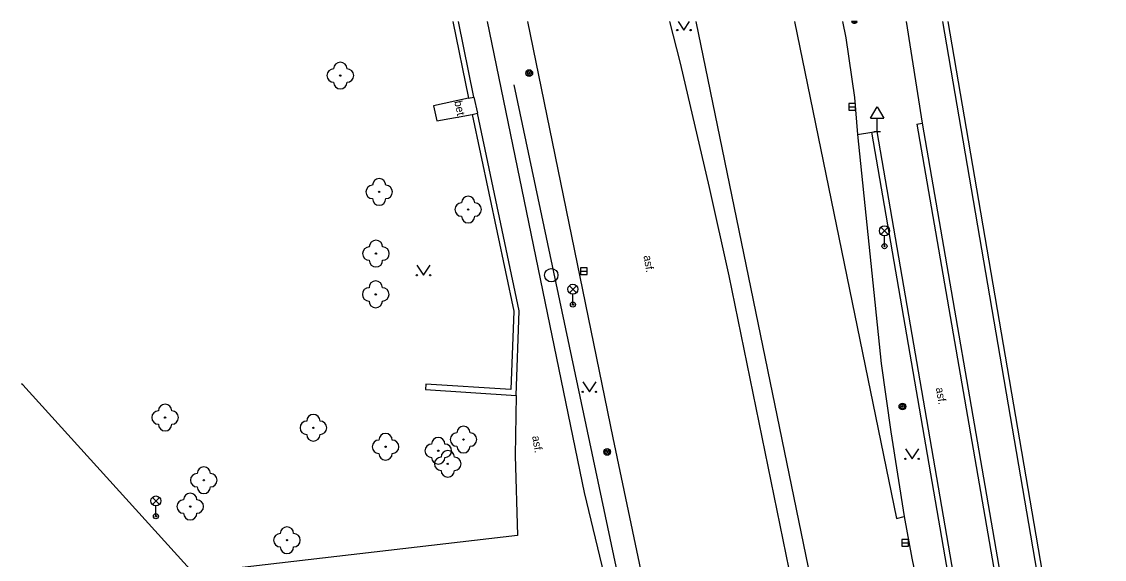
# Model space of a CAD drawing. Extents: x -640201 to -639641, y -1044739 to -1044317.
# Drawn here: x -640198.6 to -640117.4, y -1044357.3 to -1044317 of the extents above; entities that cross this region are included whole.
import ezdxf

# ---------------------------------------------------------------- set-up
doc = ezdxf.new("R2010")
doc.units = 0
for name, color, linetype in [('Ploty', 7, 'Continuous'), ('Popis povrchů', 7, 'Continuous'), ('Rozhraní ploch 1', 7, 'Continuous'), ('Rozhraní ploch 2', 7, 'Continuous'), ('Sloupy_označník', 7, 'Continuous'), ('Zeleň - stromy', 7, 'Continuous'), ('Znaky doprava', 7, 'Continuous'), ('Znaky kanalizace', 7, 'Continuous'), ('Značky doprava', 7, 'Continuous'), ('Značky KM', 7, 'Continuous')]:
    doc.layers.add(name, color=color, linetype=linetype)

msp = doc.modelspace()

# ---------------------------------------------------------------- linework, layer by layer
at = {"layer": 'Ploty'}
for p, q in [((-640117.81, -1044385.35), (-640129.52, -1044317.039)), ((-640117.416, -1044385.282), (-640129.115, -1044317.039)), ((-640161.67, -1044321.76), (-640153.53, -1044360.18))]:
    msp.add_line(p, q, dxfattribs=at)
at = {"layer": 'Rozhraní ploch 1'}
for p, q in [((-640166.227, -1044317.039), (-640165.06, -1044322.78)), ((-640164.67, -1044322.69), (-640165.816, -1044317.039)), ((-640163.663, -1044317.039), (-640156.4, -1044352.32)), ((-640160.645, -1044317.039), (-640154.26, -1044348.23)), ((-640149.17, -1044320.16), (-640149.983, -1044317.039)), ((-640148.017, -1044317.039), (-640139.43, -1044358.78)), ((-640137.033, -1044317.039), (-640136.79, -1044318.26)), ((-640136.79, -1044318.26), (-640136.13, -1044322.73)), ((-640147.01, -1044329.47), (-640149.17, -1044320.16)), ((-640165.06, -1044322.78), (-640164.67, -1044322.69)), ((-640164.67, -1044322.69), (-640164.38, -1044323.9)), ((-640136.13, -1044322.73), (-640135.91, -1044325.49)), ((-640164.78, -1044323.99), (-640164.38, -1044323.9)), ((-640164.78, -1044323.99), (-640161.66, -1044338.74)), ((-640161.26, -1044338.71), (-640164.38, -1044323.9)), ((-640135.91, -1044325.49), (-640134.83, -1044325.32)), ((-640135.91, -1044325.49), (-640134.14, -1044342.66)), ((-640145.53, -1044336.09), (-640147.01, -1044329.47)), ((-640133.97, -1044392.45), (-640145.53, -1044336.09)), ((-640161.66, -1044338.74), (-640161.89, -1044344.61)), ((-640161.5, -1044345.05), (-640161.26, -1044338.71)), ((-640134.14, -1044342.66), (-640133.42, -1044347.78)), ((-640198.47, -1044344.26), (-640198.551, -1044344.171)), ((-640185.68, -1044358.36), (-640198.47, -1044344.26)), ((-640168.26, -1044344.19), (-640168.28, -1044344.6)), ((-640168.28, -1044344.6), (-640161.5, -1044345.05)), ((-640161.89, -1044344.61), (-640168.26, -1044344.19)), ((-640161.5, -1044345.05), (-640161.58, -1044349.55)), ((-640133.42, -1044347.78), (-640132.42, -1044354.12)), ((-640154.26, -1044348.23), (-640149.89, -1044368.95)), ((-640161.58, -1044349.55), (-640161.39, -1044355.53)), ((-640156.4, -1044352.32), (-640154.493, -1044360.164)), ((-640132.42, -1044354.12), (-640131.84, -1044357.24)), ((-640161.39, -1044355.53), (-640185.68, -1044358.36)), ((-640131.84, -1044357.24), (-640125.11, -1044389.4))]:
    msp.add_line(p, q, dxfattribs=at)
at = {"layer": 'Rozhraní ploch 2'}
for p, q in [((-640140.636, -1044317.039), (-640133, -1044354.26)), ((-640132.275, -1044317.039), (-640131.08, -1044324.64)), ((-640165.06, -1044322.78), (-640167.68, -1044323.35)), ((-640167.68, -1044323.35), (-640167.44, -1044324.46)), ((-640167.44, -1044324.46), (-640164.78, -1044323.99)), ((-640134.83, -1044325.32), (-640134.45, -1044325.26)), ((-640128.02, -1044364.74), (-640134.83, -1044325.32)), ((-640127.642, -1044364.668), (-640134.45, -1044325.26)), ((-640131.46, -1044324.72), (-640131.08, -1044324.64)), ((-640131.46, -1044324.72), (-640124.631, -1044364.093)), ((-640131.08, -1044324.64), (-640124.25, -1044364.02)), ((-640133, -1044354.26), (-640132.42, -1044354.12))]:
    msp.add_line(p, q, dxfattribs=at)
at = {"layer": 'Sloupy_označník'}
for points in [[(-640135.936, -1044317.039), (-640136.364, -1044317.039)], [(-640136.058, -1044317.039), (-640136.242, -1044317.039)]]:
    msp.add_lwpolyline(points, dxfattribs=at)
for centre, radius in [((-640160.51, -1044320.89), 0.25), ((-640160.51, -1044320.89), 0.158), ((-640160.51, -1044320.89), 0.05), ((-640132.55, -1044345.88), 0.25), ((-640132.55, -1044345.88), 0.158), ((-640132.55, -1044345.88), 0.05), ((-640154.67, -1044349.28), 0.25), ((-640154.67, -1044349.28), 0.158), ((-640154.67, -1044349.28), 0.05)]:
    msp.add_circle(centre, radius, dxfattribs=at)
for radius, start, end in [(0.25, 211.01415, 328.98585), (0.158, 234.55586, 305.44414)]:
    msp.add_arc((-640136.15, -1044316.91), radius, start, end, dxfattribs=at)
at = {"layer": 'Zeleň - stromy'}
for centre in [(-640174.67, -1044321.08), (-640171.76, -1044329.8), (-640165.09, -1044331.12), (-640172, -1044334.42), (-640172.02, -1044337.47), (-640187.8, -1044346.7), (-640176.69, -1044347.47), (-640171.28, -1044348.89), (-640165.44, -1044348.35), (-640167.33, -1044349.19), (-640166.62, -1044350.17), (-640184.9, -1044351.4), (-640185.92, -1044353.37), (-640178.67, -1044355.89)]:
    msp.add_circle(centre, 0.05, dxfattribs=at)
for centre, start, end in [((-640174.67, -1044320.58), 0, 180), ((-640175.17, -1044321.08), 90, 270), ((-640174.17, -1044321.08), 270, 90), ((-640174.67, -1044321.58), 180, 0), ((-640172.26, -1044329.8), 90, 270), ((-640171.76, -1044329.3), 0, 180), ((-640171.26, -1044329.8), 270, 90), ((-640171.76, -1044330.3), 180, 0), ((-640165.09, -1044330.62), 0, 180), ((-640165.59, -1044331.12), 90, 270), ((-640164.59, -1044331.12), 270, 90), ((-640165.09, -1044331.62), 180, 0), ((-640172, -1044333.92), 0, 180), ((-640172.5, -1044334.42), 90, 270), ((-640171.5, -1044334.42), 270, 90), ((-640172, -1044334.92), 180, 0), ((-640172.02, -1044336.97), 0, 180), ((-640172.52, -1044337.47), 90, 270), ((-640171.52, -1044337.47), 270, 90), ((-640172.02, -1044337.97), 180, 0), ((-640187.8, -1044346.2), 0, 180), ((-640188.3, -1044346.7), 90, 270), ((-640187.3, -1044346.7), 270, 90), ((-640176.69, -1044346.97), 0, 180), ((-640187.8, -1044347.2), 180, 0), ((-640177.19, -1044347.47), 90, 270), ((-640176.19, -1044347.47), 270, 90), ((-640165.44, -1044347.85), 0, 180), ((-640176.69, -1044347.97), 180, 0), ((-640171.28, -1044348.39), 0, 180), ((-640165.94, -1044348.35), 90, 270), ((-640164.94, -1044348.35), 270, 90), ((-640171.78, -1044348.89), 90, 270), ((-640170.78, -1044348.89), 270, 90), ((-640167.83, -1044349.19), 90, 270), ((-640167.33, -1044348.69), 0, 180), ((-640166.83, -1044349.19), 270, 90), ((-640165.44, -1044348.85), 180, 0), ((-640171.28, -1044349.39), 180, 0), ((-640167.33, -1044349.69), 180, 0), ((-640167.12, -1044350.17), 90, 270), ((-640166.62, -1044349.67), 0, 180), ((-640166.12, -1044350.17), 270, 90), ((-640184.9, -1044350.9), 0, 180), ((-640185.4, -1044351.4), 90, 270), ((-640184.4, -1044351.4), 270, 90), ((-640166.62, -1044350.67), 180, 0), ((-640184.9, -1044351.9), 180, 0), ((-640186.42, -1044353.37), 90, 270), ((-640185.92, -1044352.87), 0, 180), ((-640185.42, -1044353.37), 270, 90), ((-640185.92, -1044353.87), 180, 0), ((-640179.17, -1044355.89), 90, 270), ((-640178.67, -1044355.39), 0, 180), ((-640178.17, -1044355.89), 270, 90), ((-640178.67, -1044356.39), 180, 0)]:
    msp.add_arc(centre, 0.5, start, end, dxfattribs=at)
at = {"layer": 'Znaky doprava'}
for p, q in [((-640134.155, -1044332.445), (-640133.625, -1044332.975)), ((-640134.155, -1044332.975), (-640133.625, -1044332.445)), ((-640133.89, -1044333.86), (-640133.89, -1044333.085)), ((-640157.505, -1044336.825), (-640156.975, -1044337.355)), ((-640157.505, -1044337.355), (-640156.975, -1044336.825)), ((-640157.24, -1044338.24), (-640157.24, -1044337.465)), ((-640188.755, -1044352.685), (-640188.225, -1044353.215)), ((-640188.755, -1044353.215), (-640188.225, -1044352.685)), ((-640188.49, -1044354.1), (-640188.49, -1044353.325))]:
    msp.add_line(p, q, dxfattribs=at)
for centre, radius in [((-640133.89, -1044332.71), 0.375), ((-640133.89, -1044333.86), 0.19), ((-640133.89, -1044333.86), 0.05), ((-640157.24, -1044337.09), 0.375), ((-640157.24, -1044338.24), 0.19), ((-640157.24, -1044338.24), 0.05), ((-640188.49, -1044352.95), 0.375), ((-640188.49, -1044354.1), 0.19), ((-640188.49, -1044354.1), 0.05)]:
    msp.add_circle(centre, radius, dxfattribs=at)
at = {"layer": 'Znaky kanalizace'}
for p, q in [((-640136.57, -1044323.41), (-640136.07, -1044323.41)), ((-640156.68, -1044335.73), (-640156.18, -1044335.73)), ((-640132.58, -1044356.09), (-640132.08, -1044356.09))]:
    msp.add_line(p, q, dxfattribs=at)
for points in [[(-640136.57, -1044323.66), (-640136.07, -1044323.66), (-640136.07, -1044323.16), (-640136.57, -1044323.16)], [(-640156.68, -1044335.98), (-640156.18, -1044335.98), (-640156.18, -1044335.48), (-640156.68, -1044335.48)], [(-640132.58, -1044356.34), (-640132.08, -1044356.34), (-640132.08, -1044355.84), (-640132.58, -1044355.84)]]:
    msp.add_lwpolyline(points, close=True, dxfattribs=at)
msp.add_circle((-640158.86, -1044336.04), 0.5, dxfattribs=at)
at = {"layer": 'Značky doprava'}
for p, q in [((-640134.95, -1044324.26), (-640134.45, -1044323.41)), ((-640134.45, -1044323.41), (-640133.95, -1044324.26)), ((-640134.95, -1044324.26), (-640133.95, -1044324.26)), ((-640134.45, -1044325.26), (-640134.45, -1044324.26)), ((-640134.7, -1044325.26), (-640134.2, -1044325.26))]:
    msp.add_line(p, q, dxfattribs=at)
at = {"layer": 'Značky KM'}
for p, q in [((-640149.345, -1044317.039), (-640148.924, -1044317.67)), ((-640148.924, -1044317.67), (-640148.503, -1044317.039)), ((-640168.938, -1044335.287), (-640168.438, -1044336.037)), ((-640168.438, -1044336.037), (-640167.938, -1044335.287)), ((-640156.509, -1044344.023), (-640156.009, -1044344.773)), ((-640156.009, -1044344.773), (-640155.509, -1044344.023)), ((-640132.322, -1044349.046), (-640131.822, -1044349.796)), ((-640131.822, -1044349.796), (-640131.322, -1044349.046))]:
    msp.add_line(p, q, dxfattribs=at)
for centre in [(-640149.424, -1044317.67), (-640148.424, -1044317.67), (-640168.938, -1044336.037), (-640167.938, -1044336.037), (-640156.509, -1044344.773), (-640155.509, -1044344.773), (-640132.322, -1044349.796), (-640131.322, -1044349.796)]:
    msp.add_circle(centre, 0.05, dxfattribs=at)

# ---------------------------------------------------------------- texts
at = {"layer": 'Popis povrchů'}
for s, rotation, p in [('bet.', 281.89646, (-640166.132, -1044323.022)), ('asf.', 279.462, (-640151.95, -1044334.59)), ('asf.', 279.80139, (-640130.046, -1044344.489)), ('asf.', 279.462, (-640160.3, -1044348.11))]:
    msp.add_text(s, height=0.6, rotation=rotation, dxfattribs=at).set_placement(p)

doc.saveas('drawing.dxf')
